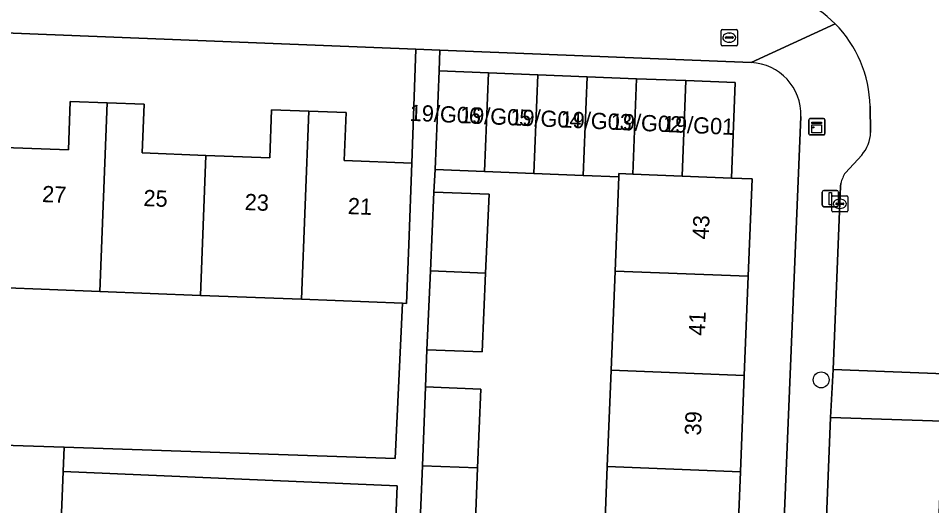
# Model space of a CAD drawing. Extents: x 161354 to 162026, y 386504 to 387460.
# Drawn here: x 161586.7 to 161642.9, y 387186.1 to 387216.1 of the extents above; entities that cross this region are included whole.
import ezdxf

# ---------------------------------------------------------------- set-up
doc = ezdxf.new("R2010")
doc.units = 0
for name, color, linetype in [('IMGEO_Boom', 7, 'Continuous'), ('IMGEO_Brandkraan', 7, 'Continuous'), ('IMGEO_Erf', 7, 'Continuous'), ('IMGEO_Kast', 7, 'Continuous'), ('IMGEO_Kolk', 7, 'Continuous'), ('IMGEO_Lichtmast', 7, 'Continuous'), ('IMGEO_Muur', 7, 'Continuous'), ('IMGEO_Pand', 7, 'Continuous'), ('IMGEO_Pand_nummerreeks', 7, 'Continuous'), ('IMGEO_Rijbaan_lokaal_open', 7, 'Continuous'), ('IMGEO_Voetpad_open', 7, 'Continuous')]:
    doc.layers.add(name, color=color, linetype=linetype)

msp = doc.modelspace()

# ---------------------------------------------------------------- linework, layer by layer
at = {"layer": 'IMGEO_Boom'}
msp.add_circle((161636.129, 387193.845), 0.489, dxfattribs=at)
at = {"layer": 'IMGEO_Brandkraan'}
for p, q in [((161630.051, 387215.396), (161630.903, 387215.396)), ((161629.976, 387214.47), (161629.976, 387215.322)), ((161630.235, 387214.89), (161630.235, 387214.902)), ((161630.673, 387214.853), (161630.275, 387214.853)), ((161630.278, 387214.939), (161630.676, 387214.939)), ((161630.464, 387215.176), (161630.489, 387215.176)), ((161630.719, 387214.902), (161630.719, 387214.89)), ((161630.977, 387215.322), (161630.977, 387214.47)), ((161630.903, 387214.396), (161630.051, 387214.396)), ((161630.487, 387214.616), (161630.462, 387214.616))]:
    msp.add_line(p, q, dxfattribs=at)
for points in [[(161630.051, 387215.396), (161630.903, 387215.396)], [(161629.976, 387214.47), (161629.976, 387215.322)], [(161630.977, 387215.322), (161630.977, 387214.47)], [(161630.903, 387214.396), (161630.051, 387214.396)]]:
    msp.add_lwpolyline(points, dxfattribs=at)
for centre, radius, start, end in [((161630.053, 387215.32), 0.0765, 91.552, 178.448), ((161630.053, 387215.32), 0.0765, 91.552, 178.448), ((161630.901, 387215.32), 0.0765, 1.552, 88.448), ((161630.901, 387215.32), 0.0765, 1.552, 88.448), ((161630.275, 387214.899), 0.0403, 85.8775, 175.7526), ((161630.272, 387214.889), 0.0366, 178.938, 274.7102), ((161630.676, 387214.896), 0.043, 264.8664, 352.4533), ((161630.68, 387214.901), 0.0386, 1.7309, 96.639), ((161630.053, 387214.472), 0.0765, 181.552, 268.448), ((161630.053, 387214.472), 0.0765, 181.552, 268.448), ((161630.901, 387214.472), 0.0765, 271.552, 358.448), ((161630.901, 387214.472), 0.0765, 271.552, 358.448)]:
    msp.add_arc(centre, radius, start, end, dxfattribs=at)
for centre, major_axis, ratio, start_param, end_param in [((161630.463, 387214.896), (-0.387, 0.002), 0.722429, 4.712389, 7.853982), ((161630.488, 387214.896), (-0.39, 0.002), 0.717154, 1.570796, 4.712389)]:
    msp.add_ellipse(centre, major_axis=major_axis, ratio=ratio, start_param=start_param, end_param=end_param, dxfattribs=at)
at = {"layer": 'IMGEO_Erf'}
for points in [[(161611.197, 387214.187), (161529.603, 387217.441)], [(161585.88, 387208.143), (161589.814, 387207.991), (161589.93, 387210.974), (161592.2, 387210.886), (161594.469, 387210.798), (161594.353, 387207.806), (161598.275, 387207.654), (161602.196, 387207.502), (161602.31, 387210.46), (161604.602, 387210.371), (161606.894, 387210.282), (161606.779, 387207.335), (161610.944, 387207.174), (161611.197, 387214.187)], [(161631.818, 387213.364), (161612.661, 387214.128), (161612.623, 387212.855), (161615.66, 387212.734), (161618.697, 387212.614), (161621.734, 387212.493), (161624.772, 387212.372), (161627.809, 387212.252), (161630.846, 387212.131), (161630.613, 387206.255), (161631.876, 387206.205), (161631.638, 387200.215), (161631.396, 387194.115), (161631.16, 387188.184), (161630.922, 387182.206)], [(161631.729, 387133.716), (161634.872, 387210.048)], [(161622.73, 387182.532), (161622.968, 387188.509), (161623.203, 387194.44), (161623.446, 387200.54), (161623.676, 387206.337), (161621.493, 387206.424), (161618.456, 387206.544), (161615.419, 387206.665), (161612.382, 387206.785), (161612.3, 387205.395), (161615.692, 387205.259), (161615.483, 387200.411), (161615.273, 387195.566), (161611.876, 387195.702), (161611.784, 387193.411), (161615.181, 387193.275), (161614.987, 387188.432), (161614.792, 387183.586)], [(161572.553, 387190.267), (161589.556, 387189.7), (161609.924, 387189.008), (161610.367, 387198.559), (161604.148, 387198.801), (161597.937, 387199.042), (161591.744, 387199.282), (161585.542, 387199.523)], [(161609.949, 387185.29), (161610.032, 387187.33), (161589.496, 387188.206), (161587.468, 387137.733)]]:
    msp.add_lwpolyline(points, dxfattribs=at)
msp.add_arc((161631.681, 387210.174), 3.193, 357.7454, 87.5441, dxfattribs=at)
at = {"layer": 'IMGEO_Kast'}
for p, q in [((161635.364, 387208.987), (161635.364, 387209.828)), ((161635.364, 387209.828), (161635.364, 387208.987)), ((161635.439, 387209.912), (161636.28, 387209.912)), ((161636.28, 387209.912), (161635.439, 387209.912)), ((161636.364, 387209.837), (161636.364, 387208.996)), ((161636.364, 387208.996), (161636.364, 387209.837)), ((161636.289, 387208.912), (161635.448, 387208.912)), ((161635.448, 387208.912), (161636.289, 387208.912))]:
    msp.add_line(p, q, dxfattribs=at)
for points in [[(161635.559, 387209.702), (161636.159, 387209.702), (161636.159, 387209.617), (161635.559, 387209.617), (161635.559, 387209.702)], [(161635.559, 387209.527), (161636.159, 387209.527), (161636.159, 387209.038), (161635.559, 387209.038), (161635.559, 387209.527)]]:
    msp.add_lwpolyline(points, dxfattribs=at)
msp.add_circle((161635.643, 387209.376), 0.0377, dxfattribs=at)
for centre, start, end in [((161635.442, 387209.834), 92.4484, 184.2845), ((161635.442, 387209.834), 92.4484, 184.2845), ((161636.286, 387209.834), 2.4484, 94.2845), ((161636.286, 387209.834), 2.4484, 94.2845), ((161635.442, 387208.99), 182.4484, 274.2845), ((161635.442, 387208.99), 182.4484, 274.2845), ((161636.286, 387208.99), 272.4484, 4.2845), ((161636.286, 387208.99), 272.4484, 4.2845)]:
    msp.add_arc(centre, 0.0779, start, end, dxfattribs=at)
at = {"layer": 'IMGEO_Kolk'}
for p, q in [((161636.776, 387204.246), (161636.776, 387205.098)), ((161636.851, 387205.172), (161637.703, 387205.172)), ((161637.078, 387204.715), (161637.476, 387204.715)), ((161637.264, 387204.952), (161637.289, 387204.952)), ((161637.777, 387205.098), (161637.777, 387204.246)), ((161637.703, 387204.172), (161636.851, 387204.172)), ((161637.035, 387204.666), (161637.035, 387204.678)), ((161637.473, 387204.629), (161637.075, 387204.629)), ((161637.287, 387204.392), (161637.262, 387204.392)), ((161637.519, 387204.678), (161637.519, 387204.666))]:
    msp.add_line(p, q, dxfattribs=at)
for points in [[(161636.776, 387204.246), (161636.776, 387205.098)], [(161636.851, 387205.172), (161637.703, 387205.172)], [(161637.777, 387205.098), (161637.777, 387204.246)], [(161637.703, 387204.172), (161636.851, 387204.172)]]:
    msp.add_lwpolyline(points, dxfattribs=at)
for centre, radius, start, end in [((161636.853, 387205.096), 0.0765, 91.552, 178.448), ((161636.853, 387205.096), 0.0765, 91.552, 178.448), ((161637.075, 387204.675), 0.0403, 85.8775, 175.7526), ((161637.48, 387204.677), 0.0386, 1.7309, 96.639), ((161637.701, 387205.096), 0.0765, 1.552, 88.448), ((161637.701, 387205.096), 0.0765, 1.552, 88.448), ((161636.853, 387204.248), 0.0765, 181.552, 268.448), ((161636.853, 387204.248), 0.0765, 181.552, 268.448), ((161637.072, 387204.665), 0.0366, 178.938, 274.7102), ((161637.476, 387204.672), 0.043, 264.8664, 352.4533), ((161637.701, 387204.248), 0.0765, 271.552, 358.448), ((161637.701, 387204.248), 0.0765, 271.552, 358.448)]:
    msp.add_arc(centre, radius, start, end, dxfattribs=at)
for centre, major_axis, ratio, start_param, end_param in [((161637.263, 387204.672), (-0.387, 0.002), 0.722429, 4.712389, 7.853982), ((161637.288, 387204.672), (-0.39, 0.002), 0.717154, 1.570796, 4.712389)]:
    msp.add_ellipse(centre, major_axis=major_axis, ratio=ratio, start_param=start_param, end_param=end_param, dxfattribs=at)
at = {"layer": 'IMGEO_Lichtmast'}
for p, q in [((161636.196, 387204.596), (161636.196, 387205.396)), ((161636.196, 387205.396), (161636.196, 387204.596)), ((161636.296, 387205.496), (161637.086, 387205.496)), ((161637.086, 387205.496), (161636.296, 387205.496)), ((161637.186, 387205.396), (161637.186, 387204.596)), ((161637.186, 387204.596), (161637.186, 387205.396)), ((161637.086, 387204.496), (161636.296, 387204.496)), ((161636.296, 387204.496), (161637.086, 387204.496))]:
    msp.add_line(p, q, dxfattribs=at)
msp.add_lwpolyline([(161636.616, 387205.371), (161636.766, 387205.371), (161636.766, 387204.621), (161636.616, 387204.621), (161636.616, 387205.371)], dxfattribs=at)
for centre, start, end in [((161636.296, 387205.396), 90, 180), ((161636.296, 387205.396), 90, 180), ((161637.086, 387205.396), 0, 90), ((161637.086, 387205.396), 360, 90), ((161636.296, 387204.596), 180, 270), ((161636.296, 387204.596), 180, 270), ((161637.086, 387204.596), 270, 0), ((161637.086, 387204.596), 270, 0)]:
    msp.add_arc(centre, 0.1, start, end, dxfattribs=at)
at = {"layer": 'IMGEO_Muur'}
msp.add_lwpolyline([(161571.591, 387190.403), (161589.556, 387189.7)], dxfattribs=at)
at = {"layer": 'IMGEO_Pand'}
for points in [[(161615.66, 387212.734), (161612.623, 387212.855), (161612.382, 387206.785), (161615.419, 387206.665)], [(161615.419, 387206.665), (161618.456, 387206.544), (161618.697, 387212.614), (161615.66, 387212.734)], [(161618.456, 387206.544), (161621.493, 387206.424), (161621.734, 387212.493), (161618.697, 387212.614)], [(161624.772, 387212.372), (161621.734, 387212.493), (161621.493, 387206.424), (161623.676, 387206.337), (161623.684, 387206.531), (161624.538, 387206.497)], [(161624.538, 387206.497), (161627.575, 387206.376), (161627.809, 387212.252), (161624.772, 387212.372)], [(161627.575, 387206.376), (161630.613, 387206.255), (161630.846, 387212.131), (161627.809, 387212.252)], [(161592.2, 387210.886), (161589.93, 387210.974), (161589.814, 387207.991), (161585.88, 387208.143), (161585.542, 387199.523), (161591.744, 387199.282)], [(161591.744, 387199.282), (161597.937, 387199.042), (161598.275, 387207.654), (161594.353, 387207.806), (161594.469, 387210.798), (161592.2, 387210.886)], [(161597.937, 387199.042), (161604.148, 387198.801), (161604.602, 387210.371), (161602.31, 387210.46), (161602.196, 387207.502), (161598.275, 387207.654)], [(161610.944, 387207.174), (161606.779, 387207.335), (161606.894, 387210.282), (161604.602, 387210.371), (161604.148, 387198.801), (161610.367, 387198.559), (161610.61, 387198.55), (161610.751, 387202.178)], [(161624.538, 387206.497), (161623.684, 387206.531), (161623.676, 387206.337), (161623.446, 387200.54), (161631.638, 387200.215), (161631.876, 387206.205), (161630.613, 387206.255), (161627.575, 387206.376)], [(161612.3, 387205.395), (161612.088, 387200.548), (161615.483, 387200.411), (161615.692, 387205.259)], [(161615.483, 387200.411), (161612.088, 387200.548), (161611.876, 387195.702), (161615.273, 387195.566)], [(161623.446, 387200.54), (161623.203, 387194.44), (161631.396, 387194.115), (161631.638, 387200.215)], [(161631.16, 387188.184), (161631.396, 387194.115), (161623.203, 387194.44), (161622.968, 387188.509)], [(161611.784, 387193.411), (161611.59, 387188.568), (161614.987, 387188.432), (161615.181, 387193.275)], [(161614.987, 387188.432), (161611.59, 387188.568), (161611.395, 387183.722), (161614.792, 387183.586)], [(161622.968, 387188.509), (161622.73, 387182.532), (161630.922, 387182.206), (161631.16, 387188.184)]]:
    msp.add_lwpolyline(points, close=True, dxfattribs=at)
at = {"layer": 'IMGEO_Rijbaan_lokaal_open'}
for points in [[(161636.98, 387215.752), (161631.818, 387213.364)], [(161637.343, 387205.929), (161637.319, 387205.77), (161636.861, 387194.478), (161643.727, 387194.219), (161644.347, 387208.691), (161644.459, 387210.411)], [(161639.169, 387209.071), (161639.137, 387210.673)], [(161639.137, 387210.673), (161639.169, 387209.071)], [(161634.872, 387210.048), (161631.729, 387133.716), (161632.521, 387129.381)], [(161637.623, 387206.588), (161638.621, 387207.676)], [(161638.621, 387207.676), (161637.623, 387206.588)], [(161634.383, 387133.402), (161634.628, 387139.442), (161634.744, 387142.297), (161636.705, 387191.542), (161636.861, 387194.478), (161637.319, 387205.77), (161637.343, 387205.929)]]:
    msp.add_lwpolyline(points, dxfattribs=at)
for points in [[(161643.727, 387194.219), (161636.861, 387194.478), (161636.705, 387191.542), (161643.611, 387191.311), (161643.725, 387194.16)], [(161643.611, 387191.311), (161636.705, 387191.542), (161634.744, 387142.297), (161641.655, 387142.032)]]:
    msp.add_lwpolyline(points, close=True, dxfattribs=at)
for centre, radius, start, end in [((161631.774, 387210.544), 7.364, 45.0058, 85.5412), ((161631.771, 387210.542), 7.367, 1.0174, 45.0035), ((161631.771, 387210.542), 7.367, 1.0174, 45.0035), ((161631.681, 387210.174), 3.193, 357.7454, 87.5441), ((161636.977, 387209.127), 2.193, 318.5715, 358.5356), ((161636.977, 387209.127), 2.193, 318.5715, 358.5356), ((161639.243, 387205.511), 1.946, 146.3783, 167.5818), ((161639.243, 387205.511), 1.946, 146.3783, 167.5818)]:
    msp.add_arc(centre, radius, start, end, dxfattribs=at)
at = {"layer": 'IMGEO_Voetpad_open'}
for points in [[(161525.531, 387218.253), (161529.603, 387217.441), (161611.197, 387214.187), (161612.661, 387214.128), (161631.818, 387213.364), (161636.98, 387215.752)], [(161611.395, 387183.722), (161611.59, 387188.568), (161611.784, 387193.411), (161611.876, 387195.702), (161612.088, 387200.548), (161612.3, 387205.395), (161612.382, 387206.785), (161612.623, 387212.855), (161612.661, 387214.128), (161611.197, 387214.187), (161610.944, 387207.174), (161610.751, 387202.178), (161610.61, 387198.55), (161610.367, 387198.559), (161609.924, 387189.008), (161589.556, 387189.7), (161589.496, 387188.206), (161610.032, 387187.33), (161609.949, 387185.29)]]:
    msp.add_lwpolyline(points, dxfattribs=at)
msp.add_lwpolyline([(161589.496, 387188.206), (161589.556, 387189.7), (161572.553, 387190.267), (161571.587, 387190.31), (161571.53, 387188.93), (161569.449, 387138.419), (161572.538, 387138.324), (161574.269, 387180.36), (161586.166, 387179.869), (161584.444, 387137.853), (161587.468, 387137.733)], close=True, dxfattribs=at)
msp.add_arc((161631.774, 387210.544), 7.364, 45.0058, 85.5412, dxfattribs=at)

# ---------------------------------------------------------------- texts
at = {"layer": 'IMGEO_Pand_nummerreeks'}
for s, rotation, p in [('19/G06', 357.4937, (161610.797, 387209.78)), ('19/G05', 357.4937, (161613.891, 387209.645)), ('19/G04', 357.4937, (161616.985, 387209.51)), ('19/G03', 357.4937, (161620.078, 387209.374)), ('19/G02', 357.4937, (161623.166, 387209.239)), ('19/G01', 357.4937, (161626.376, 387209.099)), ('27', 357.7506, (161588.182, 387204.785)), ('25', 357.7506, (161594.413, 387204.54)), ('23', 357.7506, (161600.644, 387204.295)), ('21', 357.7483, (161606.988, 387204.047)), ('43', 87.7242, (161629.206, 387202.467)), ('41', 87.7242, (161628.971, 387196.553)), ('39', 87.7242, (161628.727, 387190.414))]:
    msp.add_text(s, height=1, rotation=rotation, dxfattribs=at).set_placement(p)

doc.saveas('drawing.dxf')
